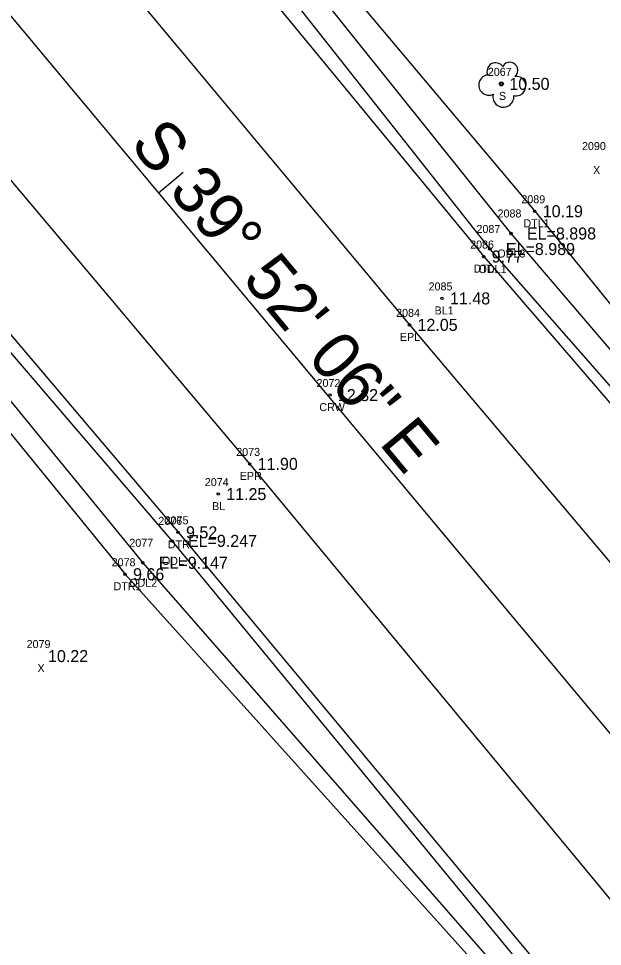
# Model space of a CAD drawing. Extents: x 2042117 to 2045853, y 303080 to 309569.
# Drawn here: x 2044220.7 to 2044293.7, y 304887 to 305002.9 of the extents above; entities that cross this region are included whole.
import ezdxf

# ---------------------------------------------------------------- set-up
doc = ezdxf.new("R2010")
doc.units = 0
for name, color, linetype in [('RD_DTM_BkLn_txCode', 7, 'Continuous'), ('RD_EX_H2O', 7, 'Continuous'), ('RD_EX_H2O_txCode', 7, 'Continuous'), ('RD_EX_Misc_txCode', 7, 'Continuous'), ('RD_EX_Road', 7, 'Continuous'), ('RD_EX_Road_txCode', 7, 'Continuous'), ('RD_EX_TX_H2O_ELEV', 7, 'Continuous'), ('RD_EX_TX_Misc_ELEV', 7, 'Continuous'), ('RD_EX_TX_Road_ELEV', 7, 'Continuous'), ('RD_EX_TX_VEG_ELEV', 7, 'Continuous'), ('RD_EX_VEG', 7, 'Continuous'), ('RD_EX_VEG_txCode', 7, 'Continuous'), ('RD_HC_Cl', 7, 'Continuous'), ('RD_HC_Data', 7, 'Continuous'), ('RD_HC_Data_Tic', 7, 'Continuous'), ('RD_HC_Survey_ELEV', 7, 'Continuous'), ('RD_HC_Survey_txCode', 7, 'Continuous'), ('RD_SMD_Locator', 7, 'Continuous')]:
    doc.layers.add(name, color=color, linetype=linetype)

msp = doc.modelspace()

# ---------------------------------------------------------------- linework, layer by layer
at = {"layer": 'RD_EX_H2O'}
for points in [[(2044033.22, 305275.98), (2044035.9, 305278.5), (2044040.04, 305277.28), (2044042.29, 305273.95), (2044048.6, 305260.29), (2044090.99, 305205.39), (2044151.22, 305127.18), (2044154.78, 305124.28), (2044202.92, 305070.22), (2044216.63, 305053.71), (2044279.58, 304974.12), (2044337.99, 304907.57), (2044344.68, 304901.99)], [(2044036.31, 305275.77), (2044038.93, 305275.76), (2044040.37, 305274.17), (2044045.78, 305258.87), (2044089.4, 305204.02), (2044149.36, 305125.44), (2044152.21, 305122.89), (2044203.11, 305065.8), (2044214.18, 305051.6), (2044278.81, 304973.18), (2044336.46, 304906.31), (2044343.82, 304899.94), (2044347.6, 304901.86)], [(2044052.64, 305262.28), (2044093.07, 305207.37), (2044155.92, 305130.37), (2044157.38, 305130.75), (2044170.33, 305147.63), (2044181.38, 305159.73), (2044197.15, 305188.95), (2044208.08, 305219.28), (2044210.72, 305219.24), (2044215.12, 305217.08), (2044202.83, 305184.83), (2044185.43, 305151.79), (2044169.6, 305138.4), (2044160.58, 305125.38), (2044211.54, 305068.64), (2044219.9, 305056.44), (2044285.19, 304978.84), (2044339.94, 304911.4), (2044347.53, 304904.82), (2044347.6, 304901.86)], [(2044211.75, 305214.4), (2044200.54, 305185.5), (2044183.75, 305152.21), (2044168.79, 305139.58), (2044158.66, 305124.96), (2044210.53, 305066.67), (2044218.51, 305055.53), (2044282.21, 304976.06), (2044339.42, 304909.19), (2044345.98, 304903.69)], [(2044111.06, 305090.52), (2044173.91, 305014.56), (2044239.84, 304937.67), (2044303.17, 304860.83), (2044366.77, 304784.1), (2044432.41, 304706.69), (2044494.93, 304630.14), (2044518.25, 304599.32)], [(2044112.24, 305091.58), (2044175.46, 305015.53), (2044240.61, 304938.74), (2044304.53, 304862.04), (2044368.54, 304785.1), (2044433.36, 304707.39), (2044496.86, 304631.9), (2044519.88, 304601.32), (2044518.57, 304598.19)], [(2044110.63, 305089.46), (2044172, 305013.36), (2044236.2, 304934.93), (2044301.9, 304859.82), (2044365.31, 304782.82), (2044429.99, 304704.43), (2044493.57, 304629.27), (2044517.33, 304598.48)], [(2044110.02, 305088.49), (2044170.14, 305011.86), (2044233.99, 304933.5), (2044300.88, 304859.21), (2044363.92, 304781.65), (2044428.82, 304703.43), (2044492.29, 304628.07), (2044516.49, 304597.96), (2044518.57, 304598.19)]]:
    msp.add_lwpolyline(points, dxfattribs=at)
at = {"layer": 'RD_EX_Road'}
for points in [[(2043522.11, 305820), (2043547.67, 305789.85), (2043610.72, 305713.32), (2043674.95, 305636.32), (2043738.18, 305559.62), (2043802.42, 305482.71), (2043865.72, 305405.84), (2043929.53, 305328.85), (2043994.13, 305253.28), (2044057.4, 305176.5), (2044121.27, 305100.2), (2044185.29, 305023.54), (2044249.56, 304947.28), (2044313.31, 304870.31), (2044377.09, 304793.29), (2044442, 304716.26), (2044505.92, 304639.55), (2044570.44, 304562.35), (2044634.61, 304485.93), (2044698.46, 304409.27), (2044762.46, 304332.37)], [(2043821.87, 305499.1), (2043885.81, 305423.07), (2043949.56, 305345.93), (2044013.41, 305270.34), (2044077.97, 305194.15), (2044141.4, 305117.67), (2044205.92, 305040.83), (2044269.54, 304964.65), (2044331.73, 304891.04), (2044335.22, 304889.2), (2044346.01, 304875.31), (2044356.18, 304867.61), (2044370.01, 304868.14), (2044386.83, 304866.36), (2044389.44, 304849.53), (2044390.71, 304830.73), (2044393.77, 304818.44), (2044395.5, 304814.18), (2044398.16, 304811.09)]]:
    msp.add_lwpolyline(points, dxfattribs=at)
at = {"layer": 'RD_EX_VEG'}
msp.add_circle((2044281.02, 304994.75), 0.25, dxfattribs=at)
for centre, radius, start, end in [((2044280.3, 304996.3), 1.08, 34.9763, 204.756), ((2044282.07, 304996.45), 0.995, 308.7626, 152.0467), ((2044279.46, 304994.6), 1.26, 96.4518, 294.734), ((2044282.86, 304994.47), 1.22, 256.5667, 98.1046), ((2044281.27, 304993.15), 1.32, 166.8827, 5.7589)]:
    msp.add_arc(centre, radius, start, end, dxfattribs=at)
at = {"layer": 'RD_HC_Cl'}
msp.add_line((2043284.3, 306123.24), (2045221.31, 303804), dxfattribs=at)
at = {"layer": 'RD_HC_Data_Tic'}
msp.add_line((2044238.18, 304981.13), (2044241.25, 304983.7), dxfattribs=at)
at = {"layer": 'RD_SMD_Locator'}
for centre in [(2044281.02, 304994.75), (2044285.19, 304978.84), (2044282.21, 304976.06), (2044279.58, 304974.12), (2044278.81, 304973.18), (2044273.6, 304967.95), (2044269.54, 304964.65), (2044259.59, 304955.88), (2044249.56, 304947.28), (2044245.63, 304943.51), (2044240.61, 304938.74), (2044239.84, 304937.67), (2044236.2, 304934.93), (2044233.99, 304933.5)]:
    msp.add_circle(centre, 0.15, dxfattribs=at)

# ---------------------------------------------------------------- texts
at = {"layer": 'RD_DTM_BkLn_txCode'}
for s, p in [('2085', (2044271.93, 304968.95)), ('BL1', (2044272.68, 304965.95)), ('2074', (2044243.96, 304944.51)), ('BL', (2044244.87, 304941.51))]:
    msp.add_text(s, height=1, dxfattribs=at).set_placement(p)
at = {"layer": 'RD_EX_H2O_txCode'}
for s, p in [('2089', (2044283.52, 304979.84)), ('2088', (2044280.55, 304978.06)), ('2087', (2044277.91, 304976.12)), ('DTL1', (2044283.78, 304976.84)), ('2086', (2044277.12, 304974.18)), ('ODL3', (2044280.52, 304973.06)), ('DTL', (2044277.56, 304971.18)), ('ODL1', (2044278.17, 304971.12)), ('2076', (2044238.15, 304939.67)), ('2075', (2044238.94, 304939.74)), ('2077', (2044234.53, 304936.93)), ('DTR', (2044239.34, 304936.74)), ('2078', (2044232.32, 304934.5)), ('ODL', (2044238.6, 304934.67)), ('ODL2', (2044234.51, 304931.93)), ('DTR1', (2044232.56, 304931.5))]:
    msp.add_text(s, height=1, dxfattribs=at).set_placement(p)
at = {"layer": 'RD_EX_Misc_txCode'}
for s, p in [('2090', (2044291.1, 304986.48)), ('X', (2044292.49, 304983.48)), ('2079', (2044221.69, 304924.28)), ('X', (2044223.05, 304921.28))]:
    msp.add_text(s, height=1, dxfattribs=at).set_placement(p)
at = {"layer": 'RD_EX_Road_txCode'}
for s, p in [('2084', (2044267.87, 304965.65)), ('EPL', (2044268.34, 304962.65)), ('2073', (2044247.89, 304948.28)), ('EPR', (2044248.33, 304945.28))]:
    msp.add_text(s, height=1, dxfattribs=at).set_placement(p)
at = {"layer": 'RD_EX_TX_H2O_ELEV'}
for s, p in [('10.19', (2044286.19, 304978.09)), ('EL=8.898', (2044284.21, 304975.31)), ('EL=8.989', (2044281.58, 304973.37)), ('9.77', (2044279.81, 304972.43)), ('9.52', (2044241.61, 304937.99)), ('EL=9.247', (2044241.84, 304936.92)), ('EL=9.147', (2044238.2, 304934.18)), ('9.66', (2044234.99, 304932.75))]:
    msp.add_text(s, height=1.5, dxfattribs=at).set_placement(p)
at = {"layer": 'RD_EX_TX_Misc_ELEV'}
for s, p in [('11.48', (2044274.6, 304967.2)), ('11.25', (2044246.63, 304942.76)), ('10.22', (2044224.36, 304922.53))]:
    msp.add_text(s, height=1.5, dxfattribs=at).set_placement(p)
at = {"layer": 'RD_EX_TX_Road_ELEV'}
for s, p in [('12.05', (2044270.54, 304963.9)), ('11.90', (2044250.56, 304946.53))]:
    msp.add_text(s, height=1.5, dxfattribs=at).set_placement(p)
at = {"layer": 'RD_EX_TX_VEG_ELEV'}
msp.add_text('10.50', height=1.5, dxfattribs=at).set_placement((2044282.02, 304994))
at = {"layer": 'RD_EX_VEG_txCode'}
for s, p in [('2067', (2044279.33, 304995.75)), ('S', (2044280.72, 304992.75))]:
    msp.add_text(s, height=1, dxfattribs=at).set_placement(p)
at = {"layer": 'RD_HC_Data'}
msp.add_text('S 39%%d 52\' 06" E', height=6, rotation=309.8684, dxfattribs=at).set_placement((2044234.45, 304987.16))
at = {"layer": 'RD_HC_Survey_ELEV'}
msp.add_text('12.32', height=1.5, dxfattribs=at).set_placement((2044260.59, 304955.13))
at = {"layer": 'RD_HC_Survey_txCode'}
for s, p in [('2072', (2044257.92, 304956.88)), ('CRW', (2044258.27, 304953.88))]:
    msp.add_text(s, height=1, dxfattribs=at).set_placement(p)

doc.saveas('drawing.dxf')
